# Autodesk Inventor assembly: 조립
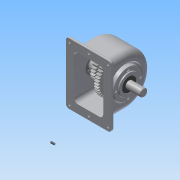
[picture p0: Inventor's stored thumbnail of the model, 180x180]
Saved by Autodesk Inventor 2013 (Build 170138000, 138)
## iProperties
Created: 2015-09
Part Number: 조립
Document SubType Name: Assembly
Designer: user-11
Author: user-11
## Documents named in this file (14)
- C:\Users\user-11\Desktop\450907V1006.dwg\조립.iam
- C:\Users\user-11\Desktop\450907V1006.dwg\본체.ipt
- C:\Users\user-11\Desktop\450907V1006.dwg\450907V1006\V-벨트풀리.ipt
- C:\Users\user-11\Desktop\450907V1006.dwg\450907V1006\뒤커버.ipt
- C:\Users\user-11\Desktop\450907V1006.dwg\450907V1006\멈춤나사 - M4x10.ipt
- C:\Users\user-11\Desktop\450907V1006.dwg\450907V1006\베어링 6203.ipt
- C:\Users\user-11\Desktop\450907V1006.dwg\450907V1006\볼트 M3 x 8.ipt
- C:\Users\user-11\Desktop\450907V1006.dwg\450907V1006\볼트 M3 x 10.ipt
- C:\Users\user-11\Desktop\450907V1006.dwg\450907V1006\스퍼기어.ipt
- C:\Users\user-11\Desktop\450907V1006.dwg\450907V1006\앞커버.ipt
- C:\Users\user-11\Desktop\450907V1006.dwg\450907V1006\오일 실 17 32 8.ipt
- C:\Users\user-11\Desktop\450907V1006.dwg\450907V1006\축.ipt
- C:\Users\user-11\Desktop\450907V1006.dwg\450907V1006\키 - 5 x 5 x 18.ipt
- C:\Users\user-11\Desktop\450907V1006.dwg\450907V1006\키 - 6 x 6 x 22.ipt
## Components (9 placed, 3 different names)
1. V-벨트풀리:1
2. ISO 4762 M3 x 10:1
3. ISO 4762 M3 x 10:2
4. ISO 4762 M3 x 10:3
5. ISO 4762 M3 x 10:4
6. ISO 4762 M3 x 8:1
7. ISO 4762 M3 x 8:2
8. ISO 4762 M3 x 8:3
9. ISO 4762 M3 x 8:4
